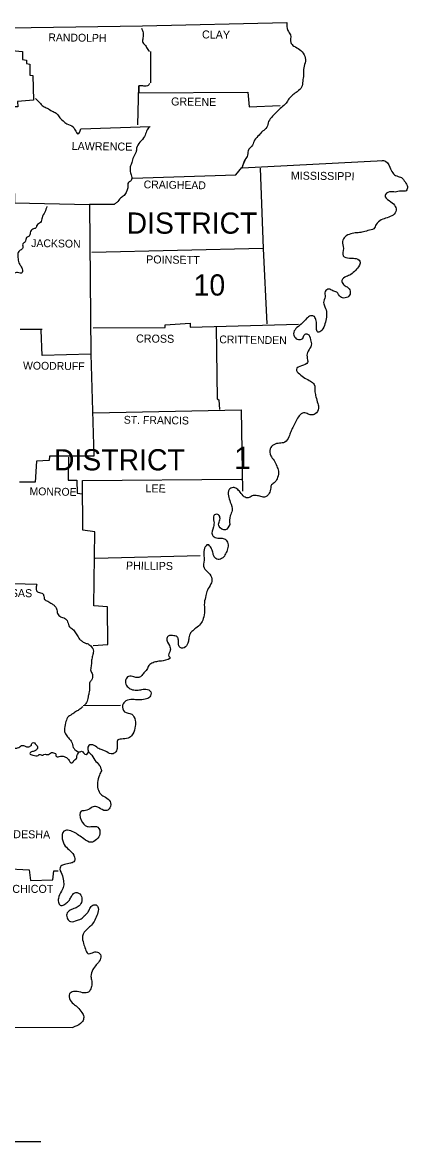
# Model space of a CAD drawing. Extents: x 21307 to 29830, y 1322443 to 1332359.
# Drawn here: x 25700 to 26073, y 1330373 to 1331455 of the extents above; entities that cross this region are included whole.
import ezdxf

# ---------------------------------------------------------------- set-up
doc = ezdxf.new("R2010")
doc.units = 0
doc.layers.add('R_Draft', color=7, linetype='Continuous')

msp = doc.modelspace()

# ---------------------------------------------------------------- linework, layer by layer
at = {"layer": 'R_Draft'}
for p, q in [((25912.9, 1331314.7), (25915, 1331321.4)), ((25913.4, 1331316.9), (25915.6, 1331322.1)), ((25698.3, 1331158.8), (25719.7, 1331158.8)), ((25759.1, 1330794.9), (25795.1, 1330795.4)), ((25124.1, 1330373.3), (25718.2, 1330373.3))]:
    msp.add_line(p, q, dxfattribs=at)
for points in [[(24968.6, 1331447), (25259.6, 1331446.8), (25515.1, 1331447.4), (25816.4, 1331452), (25956.1, 1331455.3)], [(25680.5, 1331448.8), (25679.9, 1331444.5), (25683.5, 1331443.9), (25683.4, 1331441.8), (25687.5, 1331440.9), (25687.9, 1331438), (25689.8, 1331436.7), (25690.4, 1331428.1), (25700.6, 1331427), (25700.6, 1331419.3), (25704.4, 1331418.7), (25704.4, 1331415.7), (25707.7, 1331414.8), (25707.5, 1331404.3), (25710.4, 1331403.8), (25711.1, 1331380.2), (25695.8, 1331378.8), (25696, 1331373.7), (25691.3, 1331373.6), (25692.9, 1331280.7), (25765.4, 1331279.1), (25766.7, 1331134.7), (25719.4, 1331133.4), (25718.5, 1331157.7)], [(25824.3, 1331427.2), (25824.3, 1331396.8)], [(25812.1, 1331356.3), (25813, 1331393.9), (25813, 1331387.2), (25918.3, 1331387.8), (25919.7, 1331373.7), (25949.4, 1331374.8)], [(25757, 1331352.3), (25823.8, 1331354.7)], [(25912.9, 1331314.7), (26049.5, 1331321.7)], [(25806.7, 1331304.8), (25906.6, 1331308), (25912.5, 1331314.9)], [(25930.1, 1331314.5), (25933.2, 1331236.6), (25936.8, 1331164)], [(25789, 1331279.4), (25767.1, 1331279.4), (25765.4, 1331279.1)], [(25933.2, 1331236.6), (25767.4, 1331232.8)], [(25768.9, 1331159.9), (25838.3, 1331160.3), (25838.5, 1331162.8), (25862.6, 1331164.6), (25862.6, 1331160.8), (25967.4, 1331163.7)], [(25887.8, 1331160.8), (25888.7, 1331091.5), (25890.4, 1331090.4), (25890.9, 1331081.1)], [(25887.8, 1331160.8), (25888.7, 1331091.5), (25890.4, 1331090.4), (25890.9, 1331081.1)], [(25887.8, 1331160.8), (25888.7, 1331091.5), (25890.4, 1331090.4), (25890.9, 1331081.1)], [(25887.8, 1331160.8), (25888.7, 1331091.5), (25890.4, 1331090.4), (25890.9, 1331081.1)], [(25887.8, 1331160.8), (25888.7, 1331091.5), (25890.4, 1331090.4), (25890.9, 1331081.1)], [(25766.7, 1331134.7), (25769.4, 1331036.1), (25726.6, 1331035.9), (25726.4, 1331031.9), (25714, 1331031.2), (25712.9, 1331010.7), (25697.8, 1331010.7)], [(25768.9, 1331078), (25911.8, 1331080.9)], [(25911.8, 1331080.9), (25913.2, 1331002)], [(25911.8, 1331080.9), (25913.2, 1331002)], [(25911.8, 1331080.9), (25913.2, 1331002)], [(25911.8, 1331080.9), (25913.2, 1331002)], [(25911.8, 1331080.9), (25913.2, 1331002)], [(25911.8, 1331080.9), (25913.2, 1331002)], [(25911.8, 1331080.9), (25913.2, 1331002)], [(25911.8, 1331080.9), (25913.2, 1331002)], [(25744.9, 1331035), (25744.7, 1331012.7), (25753, 1331012.7), (25753.4, 1331000.2), (25758.6, 1330999.7)], [(25768.9, 1330853), (25782.9, 1330853.9), (25782.7, 1330890.4), (25769.6, 1330891.3), (25770.3, 1330962.8), (25759, 1330964.4), (25758.6, 1331012.5), (25912.1, 1331013.6)], [(25770.7, 1330937.4), (25872.2, 1330939.9)], [(25714.3, 1330912), (25646.3, 1330913.8), (25645.9, 1330891.7), (25508.2, 1330891.2)], [(25754.8, 1330750), (25756.4, 1330750.2), (25757.6, 1330750.7), (25759, 1330750.3), (25759.4, 1330749.1), (25760.7, 1330747.9), (25762.2, 1330747.7), (25763.3, 1330748.6), (25764.5, 1330750)], [(25683, 1330637.5), (25707.1, 1330636.1), (25708.2, 1330625.7), (25730, 1330626.4), (25730.9, 1330635.2), (25735, 1330635.2)], [(25089.2, 1330630.5), (25089.5, 1330484.9), (25749.2, 1330483.8)]]:
    msp.add_lwpolyline(points, dxfattribs=at)
for points in [[(25815.5, 1331449.7), (25817.1, 1331445.2), (25816.9, 1331440.3), (25816.9, 1331435.8), (25819.3, 1331432.8), (25821.6, 1331429), (25823.4, 1331427.4)], [(25956.1, 1331455.3), (25957, 1331447.4), (25959.5, 1331443.2), (25959.8, 1331435.7), (25962.9, 1331432.4), (25968.1, 1331429.2), (25972.8, 1331424), (25973.9, 1331417.8), (25972.4, 1331411.5), (25972.1, 1331404.5), (25971.4, 1331398.4), (25970.3, 1331392.8), (25966, 1331388.3), (25961.8, 1331385.1), (25958, 1331381.3), (25955.3, 1331377.3), (25950.7, 1331373), (25946, 1331368.5), (25942.2, 1331364.6), (25938.4, 1331359.5), (25936.6, 1331353.9), (25932.5, 1331350), (25929.2, 1331346.4), (25924.9, 1331341.5), (25922.8, 1331336.7), (25918.6, 1331331.1), (25917.7, 1331325.7), (25915, 1331321.4), (25914.8, 1331320.6)], [(25823.6, 1331396.2), (25821.2, 1331393.9), (25816.7, 1331393.9), (25813, 1331393.9)], [(25713.1, 1331381.8), (25717, 1331377.7), (25720.4, 1331374.3), (25724.4, 1331372.3), (25729.1, 1331369.6), (25733.2, 1331367.4), (25735.9, 1331364), (25739.7, 1331360.2), (25743.5, 1331357.2), (25749.4, 1331354.3), (25751.4, 1331351.2), (25754.1, 1331347.5), (25757, 1331352.3)], [(25823.2, 1331354.5), (25820.5, 1331350.2), (25818.4, 1331345.1), (25814, 1331339.4), (25810.8, 1331333.8), (25810.3, 1331330), (25807.7, 1331325), (25806.3, 1331319.9), (25804.7, 1331315.6), (25804.7, 1331311.1), (25805.9, 1331306.6), (25805.6, 1331302.5), (25802.9, 1331300.5), (25802.2, 1331295.3), (25801.1, 1331291.7), (25798.7, 1331288.1), (25795.3, 1331285.4), (25791.7, 1331281.2), (25789, 1331279.4)], [(26047.5, 1331321.5), (26049.5, 1331321.7), (26055.6, 1331315.2), (26058.3, 1331309.8), (26062.3, 1331306.8), (26066.8, 1331305.2), (26070.2, 1331301), (26072.5, 1331296.5), (26071.3, 1331292.6), (26066.2, 1331292.2), (26060.6, 1331291.3), (26055.2, 1331291.5), (26050.9, 1331287.9), (26054.9, 1331283), (26060.1, 1331278.5), (26061.5, 1331273.7), (26058.7, 1331269), (26052.9, 1331266.5), (26047.3, 1331264.3), (26042.3, 1331260), (26039.9, 1331255.8), (26034.4, 1331254), (26028.6, 1331252.4), (26023.6, 1331251.9), (26017.8, 1331250.8), (26012.2, 1331248.1), (26009.9, 1331243.4), (26010.6, 1331236.8), (26010.4, 1331229.7), (26016.4, 1331227.4), (26021.6, 1331227.2), (26026.6, 1331224.5), (26026.1, 1331220.6), (26022.3, 1331215.5), (26017.8, 1331211.6), (26013.3, 1331209.6), (26009.2, 1331205.8), (26010.6, 1331202), (26014.4, 1331199.5), (26017.1, 1331195.4), (26016.7, 1331191.6), (26012.4, 1331188.9), (26007.7, 1331190), (26004.3, 1331194.5), (26000.3, 1331195.9), (25996.9, 1331197.5), (25993, 1331195.2), (25993, 1331190), (25991.5, 1331184.4), (25992.8, 1331180.2), (25994.4, 1331174.5), (25994.2, 1331170.2), (25992.8, 1331164), (25989.7, 1331157.7), (25986.1, 1331155.8), (25984.7, 1331162.6), (25984, 1331168.2), (25981.8, 1331171.4), (25978.9, 1331171.6), (25975.1, 1331168.9), (25971, 1331164.8), (25965.8, 1331160.3), (25962.7, 1331155.8), (25964.3, 1331150.2), (25968.3, 1331148.7), (25971.4, 1331149.8), (25973, 1331153.4), (25976, 1331154), (25978.9, 1331148.4)], [(25724.2, 1331277.4), (25722.1, 1331271.9), (25719.5, 1331266.5), (25717.9, 1331261.8), (25714.5, 1331259.1), (25713.4, 1331256.6), (25710.4, 1331255.5), (25708, 1331251.9), (25706.9, 1331248.6), (25704.4, 1331247.2), (25703.2, 1331243.2), (25700.8, 1331241.1), (25701, 1331237.5), (25698.3, 1331235), (25696.1, 1331232.1), (25696.1, 1331228.1), (25697, 1331222.9), (25698.8, 1331219.8), (25700.5, 1331215.9), (25700.3, 1331213.4), (25695.8, 1331213.4), (25692, 1331212.6)], [(25978.9, 1331148.4), (25979.6, 1331143.2), (25976.6, 1331137.6), (25975.5, 1331132), (25976, 1331126.4), (25970.3, 1331123.4), (25965.2, 1331119.8), (25968.1, 1331115.4), (25973.5, 1331111.5), (25978.9, 1331108.4), (25982.3, 1331105.4), (25983.2, 1331098), (25984.1, 1331093.3), (25985.9, 1331086.8), (25986.7, 1331082.3), (25983.4, 1331076.9), (25979.6, 1331075.8), (25975.7, 1331077.1), (25971, 1331077.5), (25967.2, 1331073.9), (25964.5, 1331068.8), (25961.8, 1331063.8), (25959.8, 1331059.5), (25957.9, 1331054.8), (25953.9, 1331049.4), (25949, 1331048.5), (25943.3, 1331047), (25939.9, 1331043.1), (25940.4, 1331036.4), (25943.6, 1331031.9), (25946.2, 1331026.3), (25948, 1331021.5), (25947.1, 1331015.4), (25944.5, 1331010.9), (25941.3, 1331008.2), (25939.9, 1331002.4), (25937.5, 1330998.1), (25935.4, 1330996.6), (25931, 1330997), (25926.4, 1330997.9), (25922.4, 1330997.5), (25918.6, 1330995.6), (25914.8, 1330996.8), (25910.9, 1331001.1), (25907.6, 1331004.4), (25904, 1331005.6), (25900.3, 1331003.7), (25899.5, 1330997.7), (25901.3, 1330991.6), (25903, 1330983.3), (25901.3, 1330978.3), (25900.8, 1330970)], [(25900.8, 1330970), (25896.7, 1330964.8), (25890.5, 1330968), (25890.5, 1330972.3), (25891.4, 1330976.8), (25889.3, 1330979.7), (25885.5, 1330978.5), (25885.5, 1330972.9), (25885.1, 1330967.5), (25884.1, 1330959.7), (25886.6, 1330957.4), (25892.3, 1330956.7), (25896.5, 1330955.6), (25899, 1330951.5), (25898.8, 1330946.4), (25896.8, 1330941.6), (25894, 1330937.6), (25889.5, 1330936.2), (25885.9, 1330938.5), (25884.4, 1330943.2), (25882.8, 1330947.3), (25879.7, 1330950.4), (25876.5, 1330947), (25875.8, 1330940.7), (25876, 1330935.3), (25876, 1330927.9), (25880.6, 1330923), (25883.5, 1330917.4), (25882.6, 1330912.4), (25879.2, 1330906.5), (25877.8, 1330901.2), (25876.3, 1330894.2), (25876.5, 1330886.5), (25875.2, 1330878.9), (25872.7, 1330873.9), (25868, 1330869.7), (25865, 1330867), (25862.5, 1330864.3), (25861.2, 1330858.9), (25860.3, 1330855.2), (25856.9, 1330850.7), (25854.2, 1330850.3), (25852, 1330852.1), (25851.3, 1330855.2), (25851.3, 1330858.2), (25849.9, 1330861.3), (25845.4, 1330862.5), (25841.8, 1330862.4), (25840.1, 1330859.8), (25842.5, 1330852.8), (25843.4, 1330848.3), (25842.1, 1330842.2), (25842.8, 1330841.5), (25836.4, 1330838.1), (25831.1, 1330837.5), (25826.8, 1330836.3), (25822.7, 1330833.6), (25820.7, 1330829.6), (25817.8, 1330826.4), (25815.3, 1330823.3), (25811.9, 1330821.9), (25808.1, 1330822.6), (25803.1, 1330823.1), (25800.2, 1330819.5), (25801.1, 1330814.3), (25804.5, 1330811.2), (25809.5, 1330809.8), (25814.8, 1330810.2), (25819.8, 1330810.7), (25824.5, 1330808.2), (25823.6, 1330803.3), (25819.1, 1330801), (25812.4, 1330800.3), (25807, 1330800.8), (25800.5, 1330799.4), (25797.3, 1330795.2), (25799.1, 1330788.9), (25806.1, 1330786.4), (25809.4, 1330780.5), (25809.5, 1330774.9), (25807.2, 1330767.5), (25804, 1330764.1), (25797.7, 1330762.6), (25792.8, 1330761.7), (25792.1, 1330753.5), (25789.9, 1330749.3), (25786.1, 1330748.1), (25780.7, 1330750.8), (25777.5, 1330752), (25773.5, 1330753.8), (25768.5, 1330756.9), (25764.7, 1330756.3), (25765.8, 1330748.4), (25766.2, 1330748.1), (25770.5, 1330742.1), (25774.8, 1330737.4), (25776.8, 1330731.9)], [(25714.3, 1330912), (25714.9, 1330904.7), (25719.2, 1330903.6), (25721, 1330901.6), (25721.9, 1330897.5), (25724.9, 1330895.7), (25729.1, 1330893.1), (25731.6, 1330891.3), (25733.4, 1330888.5), (25734.5, 1330883.8), (25737.4, 1330880.7), (25741.3, 1330879.3), (25744.2, 1330875.9), (25746, 1330871), (25748.9, 1330868.8), (25751.8, 1330865.1), (25753.2, 1330863.4), (25755.7, 1330859.1), (25758.2, 1330857), (25760, 1330855.7), (25762.9, 1330854.8), (25766.5, 1330852.5), (25768.9, 1330848.9), (25768.9, 1330846.2), (25768, 1330842), (25767.2, 1330837.7), (25766.9, 1330832.8), (25766.5, 1330828.5), (25768.1, 1330824.9), (25767.2, 1330819.5), (25765.4, 1330816.6), (25765.3, 1330812.7), (25764.7, 1330806.7), (25764, 1330803.3), (25762.4, 1330797.7), (25760, 1330794.9)], [(25645.9, 1330819), (25648.6, 1330817.2), (25652.4, 1330817.4), (25654.9, 1330818.4), (25656.9, 1330818.3), (25659.6, 1330816.6), (25661.4, 1330814.5), (25662.7, 1330812.9), (25663.6, 1330810.3), (25663.6, 1330808), (25664.5, 1330804.8), (25665.5, 1330803.5), (25667, 1330801.2), (25667.9, 1330799), (25668.4, 1330797.6), (25670.4, 1330795.2), (25672.2, 1330795.4), (25673.8, 1330795.2), (25676, 1330794), (25679.2, 1330791.4), (25679.8, 1330790.7), (25681.9, 1330786), (25682.3, 1330783.2), (25682.6, 1330779.4), (25683.4, 1330775.8), (25684.8, 1330771.8), (25685.5, 1330769.1), (25687.1, 1330765.3), (25688.2, 1330762.8), (25689.7, 1330759.6), (25691.8, 1330756), (25692.7, 1330753.8), (25695.8, 1330754), (25697.9, 1330754.9), (25699.6, 1330756.3), (25701.5, 1330756.2), (25703.7, 1330755.4), (25706.6, 1330754.9), (25708.4, 1330756), (25709.3, 1330756.7), (25709.5, 1330758.3), (25711.1, 1330759.2), (25712.9, 1330758), (25714.9, 1330755.1), (25714.9, 1330753.3), (25714.1, 1330752.2), (25711.8, 1330750.8), (25708.6, 1330749.7), (25707.7, 1330748.4), (25710.7, 1330747), (25715.6, 1330746.6), (25716.8, 1330747.7), (25720.1, 1330746.8), (25721.3, 1330747.7), (25725.7, 1330747.5), (25727.6, 1330749), (25731.6, 1330748.8), (25732.9, 1330747.9), (25732.9, 1330746.3), (25736.1, 1330745.5), (25738.4, 1330746.1), (25741.5, 1330745.2), (25744.2, 1330743.7), (25745.6, 1330741.8), (25747.4, 1330739.6), (25749.1, 1330740.1), (25750.3, 1330741.8), (25753, 1330744.6), (25753, 1330746.4), (25753.7, 1330747.7), (25754.6, 1330749.5)], [(25758.8, 1330793.8), (25755, 1330790.7), (25751.8, 1330788.9), (25748.3, 1330786.4), (25744.2, 1330783.3), (25742.2, 1330778.1), (25741.1, 1330770.9), (25742.6, 1330766.6), (25745.8, 1330762.8), (25748, 1330759.8), (25749.6, 1330754.4), (25753.6, 1330750.6), (25754.8, 1330750)], [(25776.8, 1330731.9), (25775, 1330727.7), (25773, 1330720.5), (25773.5, 1330714.4), (25776.2, 1330709.2), (25780.6, 1330706.3), (25785.2, 1330702.2), (25784.9, 1330695.9), (25782.2, 1330693.5), (25775.9, 1330695.1), (25771, 1330697.3), (25766.9, 1330696), (25761.3, 1330693.3), (25757.2, 1330692.8), (25757.3, 1330684.2), (25762.9, 1330678), (25767.8, 1330678), (25773.4, 1330677.3), (25775.3, 1330670.8), (25772.1, 1330665.4), (25766.7, 1330662.7), (25759.9, 1330666), (25755, 1330669.4), (25750.1, 1330672.6), (25744, 1330674.3), (25740.6, 1330673.5), (25739, 1330666), (25741.9, 1330659.1), (25746.5, 1330654.5), (25750.9, 1330648.3), (25750.1, 1330643.8), (25746.9, 1330642.6), (25741.1, 1330641.3), (25737.7, 1330639.5), (25736.8, 1330638.1), (25738.6, 1330632), (25740.2, 1330625.3), (25740.2, 1330620.3), (25738.3, 1330615.6), (25735.2, 1330608.4), (25735.6, 1330603.7), (25737.7, 1330601.5), (25740.4, 1330602.3), (25744, 1330604.8), (25746.4, 1330607.7), (25748.3, 1330611.3), (25752.1, 1330614.3), (25756.8, 1330611.6), (25757.9, 1330606), (25755.2, 1330601.2), (25751.4, 1330599), (25746.7, 1330597.2), (25743.3, 1330593.3), (25744.2, 1330588.6), (25746.9, 1330586.1), (25753.6, 1330587.3), (25758.1, 1330589.3), (25760.6, 1330591.8), (25763.6, 1330594.9), (25765.3, 1330597.9), (25767.6, 1330601.2), (25771.7, 1330602.1), (25773.7, 1330599.4), (25773, 1330593.3), (25770.5, 1330587.5), (25767.1, 1330582.6), (25763.3, 1330579.2), (25758.6, 1330571.8), (25759.5, 1330565), (25761.3, 1330559.4), (25763.8, 1330555.1), (25768.1, 1330556), (25773, 1330556.5), (25775.9, 1330554.2), (25775.5, 1330549.2), (25771.9, 1330544.3), (25768.5, 1330539.6), (25766.7, 1330533.1), (25767.4, 1330528.6), (25767.4, 1330524.5), (25766, 1330520), (25763.5, 1330517.5), (25756.8, 1330517.7), (25749.8, 1330518.4), (25746, 1330516.2), (25746.7, 1330510.1), (25750.9, 1330505.6), (25753.7, 1330503.3), (25757.9, 1330498.2), (25759.7, 1330494.1), (25759.1, 1330490.5), (25756.6, 1330487.4), (25749.2, 1330483.8)]]:
    msp.add_spline(points, degree=3, dxfattribs=at)

# ---------------------------------------------------------------- texts
for s, height, rotation, p in [('CLAY', 7.74, 359.2258, (25874, 1331439.8)), ('RANDOLPH', 7.56, 359.2583, (25725.5, 1331437.1)), ('GREENE', 7.74, 359.2361, (25844.1, 1331375)), ('LAWRENCE', 7.74, 359.2678, (25748, 1331332)), ('MISSISSIPPI', 7.739, 359.3097, (25959.8, 1331303.4)), ('CRAIGHEAD', 7.56, 359.1159, (25817.6, 1331294.9)), ('JACKSON', 7.56, 359.1352, (25708.9, 1331238.2)), ('POINSETT', 7.74, 359.1987, (25820, 1331222.4)), ('CROSS', 7.74, 359.3839, (25810.3, 1331145.9)), ('CRITTENDEN', 7.56, 359.213, (25890.7, 1331145.1)), ('WOODRUFF', 7.56, 359.2748, (25701, 1331119.8)), ('ST. FRANCIS', 7.559, 359.2216, (25798.4, 1331067.4)), ('MONROE', 7.56, 359.0331, (25707.3, 1330998.3)), ('LEE', 7.74, 359.4327, (25819.4, 1331001)), ('PHILLIPS', 7.74, 359.3179, (25800.5, 1330926.4)), ('ARKANSAS', 7.74, 359.2678, (25653.5, 1330900.3)), ('DESHA', 7.74, 359.3704, (25691.6, 1330666.7))]:
    msp.add_text(s, height=height, rotation=rotation, dxfattribs=at).set_placement(p)
for s, height, p in [('DISTRICT', 20.52, (25801.1, 1331251)), ('10', 20.52, (25865.9, 1331191.2)), ('DISTRICT', 20.52, (25730.9, 1331022.2)), ('1', 21.6, (25905.1, 1331023.5)), ('CHICOT', 7.74, (25690.7, 1330613.8))]:
    msp.add_text(s, height=height, dxfattribs=at).set_placement(p)

doc.saveas('drawing.dxf')
